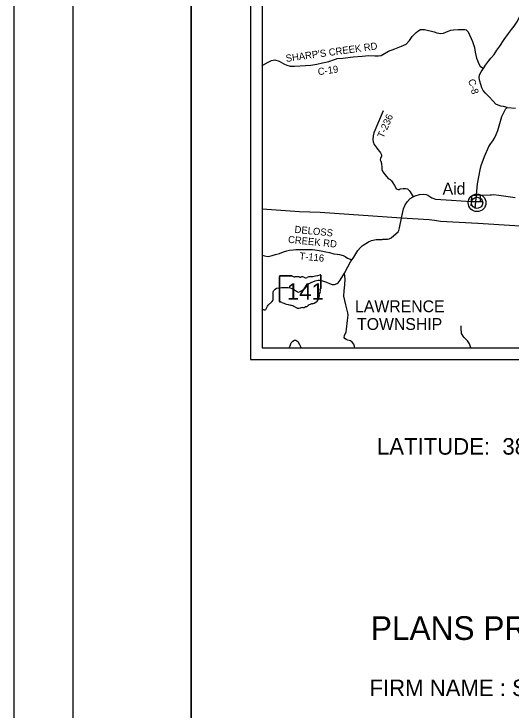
# Model space of a CAD drawing. Extents: x 0 to 34, y 0 to 22.
# Drawn here: x 0 to 4.21, y 11.04 to 16.92 of the extents above; entities that cross this region are included whole.
import ezdxf

# ---------------------------------------------------------------- set-up
doc = ezdxf.new("R2010")
doc.units = 0
for name, color, linetype in [('GM_X_County_Road', 7, 'Continuous'), ('GM_X_County_Road_Text', 7, 'Continuous'), ('GM_X_State_Route', 7, 'Continuous'), ('GM_X_State_Shield', 7, 'Continuous'), ('GM_X_Township', 7, 'Continuous'), ('GM_X_Township_Road', 7, 'Continuous'), ('GM_X_Township_Road_Text', 7, 'Continuous'), ('GM_X_Township_Subdivision', 7, 'Continuous'), ('GM_X_Township_Text', 7, 'Continuous'), ('GM_X_Unincorporated', 7, 'Continuous'), ('SH_Border', 7, 'Continuous'), ('SH_Cut_Line', 7, 'Continuous'), ('SH_Data', 7, 'Continuous'), ('SH_Masking', 7, 'Continuous'), ('SH_Text', 7, 'Continuous')]:
    doc.layers.add(name, color=color, linetype=linetype)

msp = doc.modelspace()

# ---------------------------------------------------------------- linework, layer by layer
at = {"layer": 'GM_X_County_Road'}
for points in [[(4.0336, 16.5466), (4.0388, 16.5536), (4.0613, 16.5797), (4.0854, 16.6142), (4.1095, 16.6497), (4.1485, 16.7065), (4.1848, 16.7572), (4.2085, 16.7901), (4.231, 16.8177), (4.2555, 16.8525), (4.2704, 16.8828), (4.2862, 16.9173), (4.2952, 16.9655)], [(2.1, 16.4801), (2.106, 16.4873), (2.1497, 16.5143), (2.1801, 16.5264), (2.2075, 16.5328), (2.2428, 16.5218), (2.2826, 16.5009), (2.3096, 16.4872), (2.3373, 16.4804), (2.3723, 16.4796), (2.4661, 16.4864), (2.5109, 16.4887), (2.5618, 16.497), (2.6101, 16.5087), (2.6632, 16.5197), (2.7107, 16.5368), (2.7293, 16.5425), (2.7354, 16.5444), (2.7825, 16.5485), (2.8707, 16.5599), (2.9451, 16.564), (3.0036, 16.5697), (3.053, 16.5659), (3.0853, 16.5681), (3.1058, 16.5693), (3.1213, 16.5784), (3.1685, 16.6068), (3.2232, 16.6277), (3.2779, 16.6482), (3.3189, 16.6671), (3.3452, 16.6964), (3.3699, 16.7302), (3.4037, 16.7658), (3.4163, 16.7761), (3.4398, 16.7905), (3.4732, 16.7901), (3.5553, 16.7688), (3.5789, 16.7622), (3.5952, 16.7587), (3.6096, 16.7552), (3.6327, 16.76), (3.6582, 16.7702), (3.6818, 16.7795), (3.6966, 16.7848), (3.7197, 16.7869), (3.7569, 16.7886), (3.7804, 16.7885), (3.7974, 16.7896), (3.8149, 16.7887), (3.8247, 16.7879), (3.8327, 16.7822), (3.8428, 16.7703), (3.8799, 16.6896), (3.8959, 16.6372), (3.8991, 16.6191)], [(3.8991, 16.6191), (3.9025, 16.5992), (3.9121, 16.5482), (3.9218, 16.5264), (3.9335, 16.4999), (3.9451, 16.4808), (3.9711, 16.461)], [(3.954, 16.4333), (3.9639, 16.45), (3.9711, 16.461), (3.9899, 16.4897), (4.0155, 16.5222), (4.0336, 16.5466), (4.0336, 16.5466)], [(4.1718, 16.1317), (4.1415, 16.1377), (4.1184, 16.142), (4.0957, 16.1512), (4.0764, 16.1596), (4.053, 16.1841), (4.0165, 16.2234), (3.9889, 16.2512), (3.9709, 16.2753), (3.9592, 16.2966), (3.9425, 16.3525), (3.9351, 16.3821), (3.9379, 16.4061), (3.9539, 16.4331), (3.954, 16.4333)], [(2.883, 14.1), (2.8799, 14.1104), (2.8743, 14.1301), (2.8606, 14.148), (2.8462, 14.1567), (2.8245, 14.1647), (2.812, 14.1689), (2.798, 14.178), (2.7949, 14.1856), (2.7968, 14.2042), (2.8094, 14.2327), (2.8121, 14.2555), (2.8216, 14.3303), (2.8277, 14.374), (2.8255, 14.3942), (2.8092, 14.4614), (2.791, 14.5343), (2.7926, 14.5807), (2.8006, 14.6312), (2.8014, 14.6794), (2.797, 14.7311)]]:
    msp.add_lwpolyline(points, dxfattribs=at)
at = {"layer": 'GM_X_State_Route'}
for points in [[(3.9072, 15.3345), (3.9072, 15.3345), (3.9118, 15.3905), (3.9153, 15.4231), (3.9227, 15.4855), (3.9429, 15.6034), (3.953, 15.6392), (3.9809, 15.7167), (4.0176, 15.8007), (4.0338, 15.8257), (4.0519, 15.8499), (4.0662, 15.8719), (4.0798, 15.9008), (4.094, 15.9349), (4.1046, 15.9768), (4.1276, 16.0551), (4.1441, 16.0885), (4.1577, 16.1169), (4.1718, 16.1317), (4.2417, 16.1257)], [(3.1163, 15.0159), (3.1195, 15.016), (3.1224, 15.0161), (3.16, 15.0171), (3.1737, 15.0188), (3.1901, 15.0273), (3.2345, 15.0644), (3.2498, 15.0801), (3.2571, 15.0918), (3.2627, 15.1137), (3.2794, 15.1952), (3.282, 15.208), (3.2961, 15.273), (3.309, 15.3078), (3.3291, 15.336), (3.3521, 15.3604), (3.3777, 15.3764), (3.3937, 15.3849), (3.4306, 15.3963), (3.4681, 15.3985), (3.487, 15.396), (3.5028, 15.3905), (3.5361, 15.3678), (3.5665, 15.3546), (3.7016, 15.3459)], [(4.2405, 15.367), (4.1023, 15.3866), (4.06, 15.3908), (4.0387, 15.3902), (4.0278, 15.3898), (3.9587, 15.3874), (3.9468, 15.3882), (3.9118, 15.3905)], [(3.7016, 15.3459), (3.7836, 15.3406), (3.8706, 15.336), (3.8828, 15.3355), (3.9072, 15.3345)], [(2.9407, 14.9563), (2.9468, 14.9614), (2.9537, 14.9671), (3.0003, 14.9946), (3.0242, 15.005), (3.0656, 15.0144), (3.1163, 15.0159)], [(2.3199, 14.6094), (2.3383, 14.6058), (2.365, 14.5957), (2.3906, 14.5779), (2.4, 14.5729), (2.4083, 14.5705), (2.4209, 14.5753), (2.4312, 14.5813), (2.4548, 14.5943), (2.4629, 14.6018), (2.4813, 14.6235), (2.4989, 14.6412), (2.5138, 14.6524), (2.5489, 14.6649), (2.5728, 14.6707), (2.5849, 14.6717), (2.6098, 14.6646), (2.6283, 14.6587), (2.6449, 14.6528), (2.6709, 14.6415), (2.6913, 14.6333), (2.7106, 14.6342), (2.735, 14.6426), (2.743, 14.649), (2.7592, 14.672), (2.797, 14.7311), (2.8234, 14.7831), (2.8467, 14.8246), (2.8594, 14.8434), (2.8602, 14.8445), (2.8756, 14.8652), (2.9081, 14.9217), (2.9307, 14.948), (2.9407, 14.9563)], [(2.1, 14.4284), (2.1088, 14.4237), (2.1159, 14.4202), (2.1243, 14.4201), (2.1304, 14.4231), (2.135, 14.4295), (2.1404, 14.4408), (2.1439, 14.4499), (2.1505, 14.4585), (2.1846, 14.4892), (2.19, 14.4979), (2.1931, 14.507), (2.1933, 14.5218), (2.1918, 14.5552), (2.1943, 14.5718), (2.1993, 14.5839), (2.2086, 14.5956), (2.2199, 14.6018)], [(2.2199, 14.6018), (2.2227, 14.6034), (2.2648, 14.6086), (2.3194, 14.6095), (2.3199, 14.6094)]]:
    msp.add_lwpolyline(points, dxfattribs=at)
at = {"layer": 'GM_X_State_Shield'}
for p, q in [((2.2455, 14.7029), (2.2455, 14.4903)), ((2.3514, 14.7065), (2.2489, 14.7065)), ((2.5956, 14.6006), (2.5956, 14.7118)), ((2.5955, 14.6006), (2.5956, 14.6006))]:
    msp.add_line(p, q, dxfattribs=at)
for centre, major_axis, start_param, end_param in [((2.4708, 14.9963), (0.3713, 0), 4.814394, 5.042369), ((2.5917, 14.7123), (0.0039, 0), 6.141152, 7.989035), ((2.2495, 14.7033), (0.00406, 0), 1.712693, 3.28349), ((2.3759, 14.7312), (0.0393, 0), 4.042523, 4.731795), ((2.3889, 14.5872), (0.1412, 0), 1.404758, 1.657858), ((2.421, 14.7044), (0.0113, 0), 3.836095, 5.185415), ((2.4376, 14.6799), (0.0236, 0), 0.950623, 2.079405), ((2.4681, 14.7136), (0.0284, 0), 4.081561, 5.145723), ((2.5182, 14.6416), (0.0747, 0), 1.699011, 2.107814), ((2.5947, 14.5924), (0.00603, 0), 1.883978, 3.671073), ((2.5914, 14.6002), (0.00417, 0), 5.05454, 6.418171), ((2.4916, 14.5399), (0.0929, 0), 5.101752, 6.440018), ((2.6095, 14.5541), (0.0263, 0), 2.387724, 3.262537), ((2.5563, 14.5784), (0.0362, 0), 5.934695, 6.695948), ((2.2495, 14.4898), (0.00409, 0), 3.00124, 4.508301), ((2.2501, 14.5116), (0.0312, 0), 4.665946, 4.897461), ((2.2565, 14.478), (0.0113, 0), 0.519207, 1.627899), ((2.3987, 14.669), (0.2681, 0), 4.195997, 4.488961), ((2.3187, 14.3948), (0.0839, 0), 0.823519, 1.323587), ((2.4095, 14.477), (0.0532, 0), 4.026481, 4.996735), ((2.4402, 14.4035), (0.0437, 0), 1.495662, 1.94098), ((2.4441, 14.4611), (0.0284, 0), 4.691044, 5.507374), ((2.4698, 14.4405), (0.00798, 0), 1.147584, 2.315152), ((2.4664, 14.4697), (0.03, 0), 4.937069, 5.64225), ((2.5308, 14.4306), (0.0509, 0), 1.647645, 2.488434)]:
    msp.add_ellipse(centre, major_axis=major_axis, ratio=0.8, start_param=start_param, end_param=end_param, dxfattribs=at)
at = {"layer": 'GM_X_Township'}
msp.add_lwpolyline([(4.7383, 17.0951), (4.704, 16.5887), (4.6735, 16.1378), (4.6688, 16.1067), (4.6617, 15.9964), (4.6068, 15.1539), (4.6039, 15.1106), (4.4494, 15.1194), (4.2374, 15.1315), (3.9258, 15.1493), (3.6093, 15.1673), (3.5571, 15.1752), (3.5118, 15.1797), (3.2794, 15.1952), (2.59, 15.2415), (2.4159, 15.2489), (2.1, 15.2699)], dxfattribs=at)
at = {"layer": 'GM_X_Township_Road'}
for points in [[(3.1247, 16.1013), (3.0448, 15.9165), (3.0391, 15.8896), (3.0375, 15.8592), (3.0379, 15.8391), (3.0478, 15.8189), (3.0633, 15.7954), (3.0796, 15.7749), (3.0933, 15.7574), (3.0997, 15.7471), (3.1081, 15.7316), (3.1092, 15.7202), (3.1016, 15.7004), (3.0982, 15.6875), (3.1042, 15.6754), (3.1099, 15.6575), (3.1114, 15.6233), (3.1125, 15.6032), (3.1224, 15.5835), (3.1383, 15.5645), (3.1535, 15.5447), (3.1668, 15.5295), (3.1841, 15.5221), (3.195, 15.511), (3.2045, 15.4934), (3.2199, 15.47), (3.2342, 15.446), (3.2411, 15.4412), (3.2516, 15.4371), (3.2584, 15.4383), (3.2681, 15.4425), (3.292, 15.4455), (3.3125, 15.4463), (3.33, 15.4421), (3.3437, 15.4299), (3.3524, 15.4182), (3.3777, 15.3764)], [(3.9463, 15.3351), (3.9468, 15.3882)], [(2.1, 14.8833), (2.1206, 14.8757), (2.1506, 14.8703), (2.1855, 14.879), (2.2125, 14.8874), (2.2475, 14.8965), (2.2816, 14.909), (2.309, 14.9192), (2.3322, 14.9257), (2.3626, 14.928), (2.3861, 14.9287), (2.4617, 14.9302), (2.4955, 14.9309), (2.5263, 14.9309), (2.5646, 14.9256), (2.5999, 14.9195), (2.6398, 14.9111), (2.6702, 14.9054), (2.7051, 14.894), (2.7344, 14.8894), (2.7553, 14.8879), (2.7864, 14.8799), (2.8031, 14.8712), (2.8221, 14.856), (2.8594, 14.8434)], [(3.8663, 14.1), (3.8546, 14.1339), (3.8369, 14.1591), (3.8063, 14.1896), (3.7853, 14.2194), (3.7821, 14.2612), (3.7836, 14.2858)], [(2.3288, 14.1), (2.3368, 14.1148), (2.3467, 14.1421), (2.3589, 14.1565), (2.3733, 14.1645), (2.3862, 14.1626), (2.4025, 14.1512), (2.417, 14.1277), (2.4299, 14.1)]]:
    msp.add_lwpolyline(points, dxfattribs=at)
at = {"layer": 'GM_X_Township_Subdivision'}
for points in [[(3.8702, 15.3308), (3.8706, 15.336), (3.8716, 15.3496), (3.8775, 15.3879), (3.8809, 15.3893), (3.9118, 15.3905)], [(3.8679, 15.3002), (3.8702, 15.3308)], [(3.9031, 15.2776), (3.9072, 15.3345)], [(3.9072, 15.3345), (3.9393, 15.335)], [(3.9393, 15.335), (3.9463, 15.3351), (3.9633, 15.3354)]]:
    msp.add_lwpolyline(points, dxfattribs=at)
at = {"layer": 'GM_X_Unincorporated'}
for radius in [0.0744, 0.0472]:
    msp.add_circle((3.9181, 15.3245), radius, dxfattribs=at)
at = {"layer": 'SH_Border'}
for points in [[(0.5, 21.5), (1.5, 21.5), (1.5, 0.5), (0.5, 0.5)], [(1.5, 21.5), (33.5, 21.5), (33.5, 0.5), (1.5, 0.5)]]:
    msp.add_lwpolyline(points, close=True, dxfattribs=at)
at = {"layer": 'SH_Cut_Line'}
msp.add_lwpolyline([(0, 0), (34, 0), (34, 22), (0, 22)], close=True, dxfattribs=at)
at = {"layer": 'SH_Data'}
for p, q in [((2, 21), (2, 14)), ((2.1, 20.9), (2.1, 14.1)), ((2.1, 14.1), (8.9, 14.1)), ((2.1, 14.1), (2.1, 14.1)), ((2, 14), (9, 14))]:
    msp.add_line(p, q, dxfattribs=at)
at = {"layer": 'SH_Masking'}
for p, q in [((2.2455, 14.4903), (2.2455, 14.7029)), ((2.2489, 14.7065), (2.3514, 14.7065)), ((2.5955, 14.7118), (2.5955, 14.6006)), ((2.5928, 14.597), (2.5928, 14.597))]:
    msp.add_line(p, q, dxfattribs=at)
for centre, major_axis, start_param, end_param in [((2.4708, 14.9963), (0.3713, 0), 4.814394, 5.042369), ((2.5917, 14.7123), (0.0039, 0), 6.141152, 7.989035), ((2.2495, 14.7033), (0.00406, 0), 1.712693, 3.28349), ((2.3759, 14.7312), (0.0393, 0), 4.042523, 4.731795), ((2.3889, 14.5872), (0.1412, 0), 1.404758, 1.657858), ((2.421, 14.7044), (0.0113, 0), 3.836095, 5.185415), ((2.4376, 14.6799), (0.0236, 0), 0.950623, 2.079405), ((2.4681, 14.7136), (0.0284, 0), 4.081561, 5.145723), ((2.5182, 14.6416), (0.0747, 0), 1.699011, 2.107814), ((2.5947, 14.5924), (0.00603, 0), 1.883978, 3.671073), ((2.5914, 14.6002), (0.00417, 0), 5.05454, 6.418171), ((2.4916, 14.5399), (0.0929, 0), 5.101752, 6.440018), ((2.6095, 14.5541), (0.0263, 0), 2.387724, 3.262537), ((2.5563, 14.5784), (0.0362, 0), 5.934695, 6.695948), ((2.2495, 14.4898), (0.00409, 0), 3.00124, 4.508301), ((2.2501, 14.5116), (0.0312, 0), 4.665946, 4.897461), ((2.2565, 14.478), (0.0113, 0), 0.519207, 1.627899), ((2.3987, 14.669), (0.2681, 0), 4.195997, 4.488961), ((2.3187, 14.3948), (0.0839, 0), 0.823519, 1.323587), ((2.4095, 14.477), (0.0532, 0), 4.026481, 4.996735), ((2.4402, 14.4035), (0.0437, 0), 1.495662, 1.94098), ((2.4441, 14.4611), (0.0284, 0), 4.691044, 5.507374), ((2.4698, 14.4405), (0.00798, 0), 1.147584, 2.315152), ((2.4664, 14.4697), (0.03, 0), 4.937069, 5.64225), ((2.5308, 14.4306), (0.0509, 0), 1.647645, 2.488434)]:
    msp.add_ellipse(centre, major_axis=major_axis, ratio=0.8, start_param=start_param, end_param=end_param, dxfattribs=at)

# ---------------------------------------------------------------- texts
at = {"layer": 'GM_X_County_Road_Text'}
for s, rotation, p in [("SHARP'S CREEK RD", 7.92776, (2.3034, 16.5154)), ('C-19', 7.92776, (2.5749, 16.4029)), ('C-8', 285.76995, (3.8416, 16.3619))]:
    msp.add_text(s, height=0.06, rotation=rotation, dxfattribs=at).set_placement(p)
at = {"layer": 'GM_X_State_Shield'}
msp.add_text('141', height=0.14004, dxfattribs=at).set_placement((2.3094, 14.5053))
at = {"layer": 'GM_X_Township_Road_Text'}
for s, rotation, p in [('T-236', 66.62912, (3.1265, 15.8662)), ('DELOSS', 354.24587, (2.3718, 15.0721)), ('CREEK RD', 354.24587, (2.3165, 14.9872)), ('T-116', 354.24587, (2.4128, 14.8469))]:
    msp.add_text(s, height=0.06, rotation=rotation, dxfattribs=at).set_placement(p)
at = {"layer": 'GM_X_Township_Text'}
for s, p in [('LAWRENCE', (2.8854, 14.4)), ('TOWNSHIP', (2.9028, 14.25))]:
    msp.add_text(s, height=0.1, dxfattribs=at).set_placement(p)
at = {"layer": 'GM_X_Unincorporated'}
msp.add_text('Aid', height=0.1, dxfattribs=at).set_placement((3.6263, 15.3945))
at = {"layer": 'SH_Text'}
for s, height, p in [('LATITUDE:  38°38\'06"     LONGITUDE:  82°27\'51"', 0.14, (3.071, 13.1958)), ('PLANS PREPARED BY:', 0.2, (3.0194, 11.6295)), ('FIRM NAME : SMART SECVICES, INC.', 0.14, (3.0077, 11.1543))]:
    msp.add_text(s, height=height, dxfattribs=at).set_placement(p)

doc.saveas('drawing.dxf')
